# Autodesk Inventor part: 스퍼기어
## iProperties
Created: 2011-04
Part Number: 스퍼기어
Material: Steel
Document SubType Name: Modeling
Designer: pww
Categories: <?xml version="1.0" encoding="UTF-16"?> <MemberInstance><Categories><FamilyTemplate><FamilyTemplateParameter ValueType="xs:double" Id="1" ObjectReferenceKey="da
Density: 1 g/cm^3
CustomPartVersion: 1
Author: pww
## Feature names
1. Extrusion1
